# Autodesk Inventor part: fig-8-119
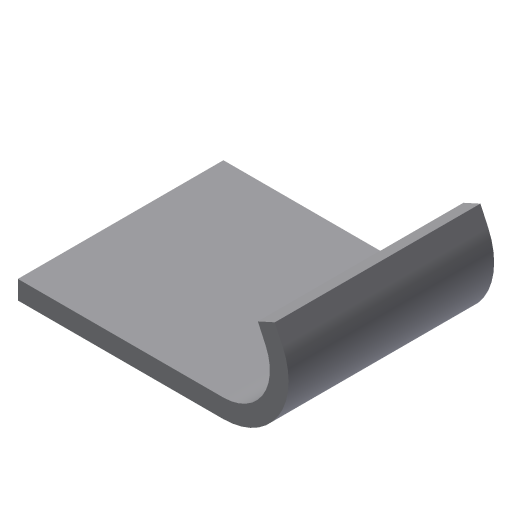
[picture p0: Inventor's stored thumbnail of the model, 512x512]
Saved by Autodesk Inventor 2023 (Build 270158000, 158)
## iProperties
Created: 2009-09
Part Number: fig-8-119
Document SubType Name: Modeling
Designer: Sham
Density: 1 g/cm^3
Material: Generic
Appearance: Default
Author: Sham
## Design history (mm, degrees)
sketch "Sketch1"
  geometry: L1 (-33.976, 22)-(0, 22); L2 (0, 22)-(0, 0); L3 (0, 0)-(-33.976, 0); L4 (-33.976, 0)-(-33.976, 22)
  constraints: 8 end point, 2 parallel, 1 horizontal, 1 perpendicular
extrude "Extrusion1" new body sketch "Sketch1" distance "d0" = 2; taper "d1" = 0 deg
sketch "Sketch2"
  geometry: L1 (-12, 22)-(-12, 0)
  constraints: 2 end point
feature "Bend Part1" sketch "Sketch2" dims "d2" = 5, "d4" = 10
body "Solid1"
